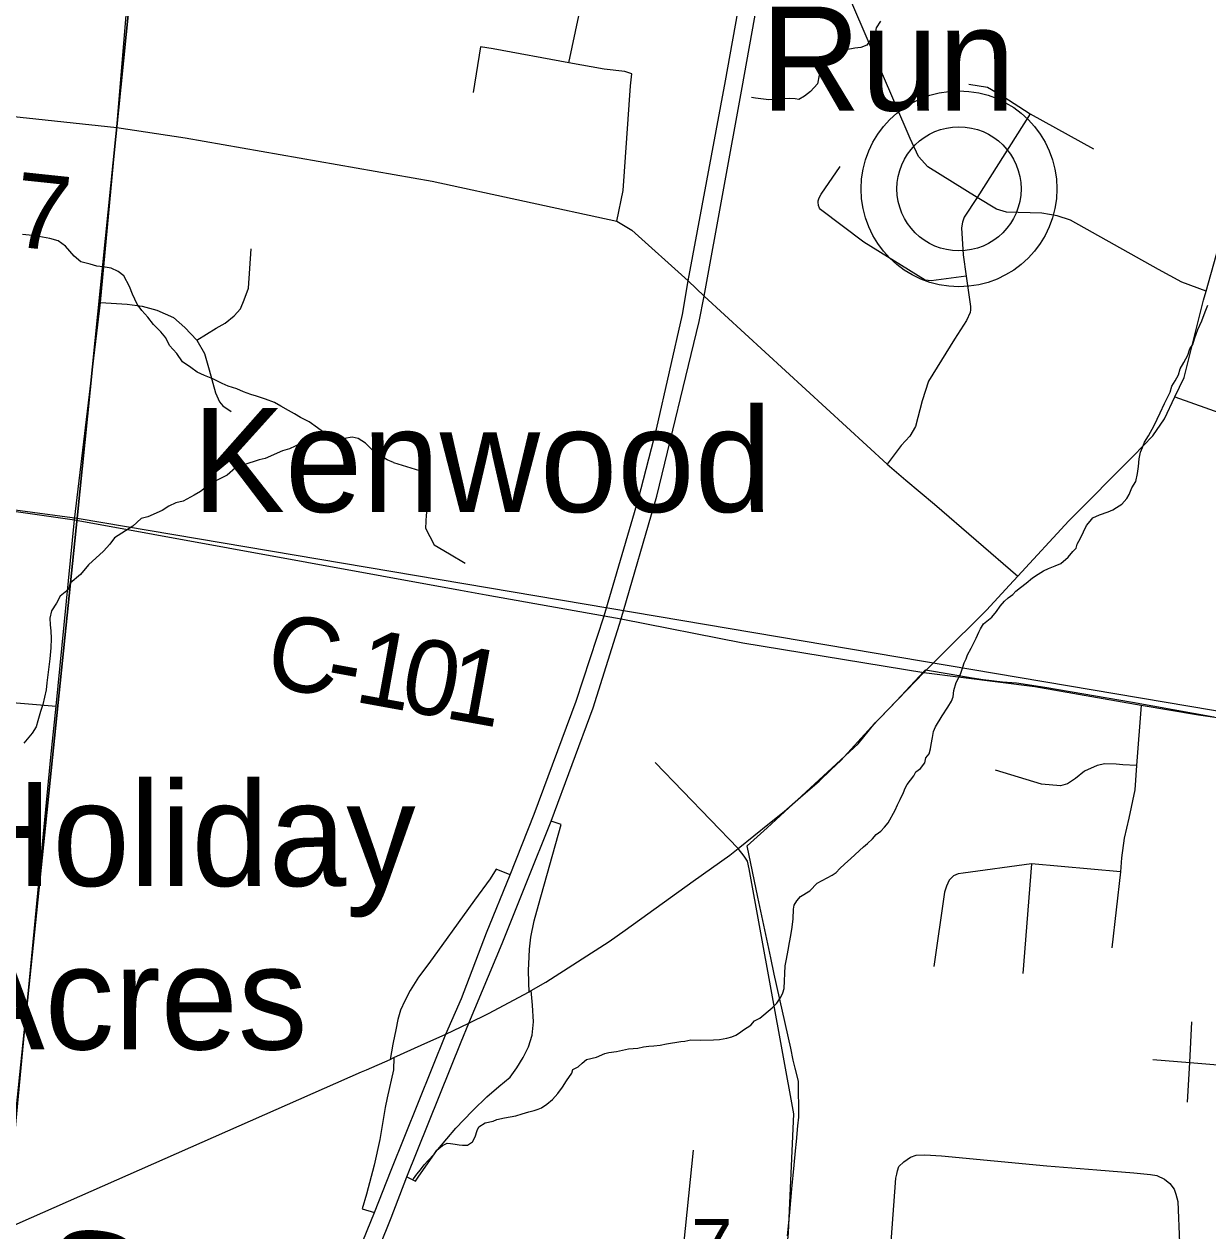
# Model space of a CAD drawing. Extents: x 0 to 34, y 0 to 22.
# Drawn here: x 3.9828 to 4.4325, y 20.1554 to 20.6139 of the extents above; entities that cross this region are included whole.
import ezdxf

# ---------------------------------------------------------------- set-up
doc = ezdxf.new("R2010")
doc.units = 0
for name, color, linetype in [('GM_X_City_Street', 7, 'Continuous'), ('GM_X_Corporation', 7, 'Continuous'), ('GM_X_County_Road', 7, 'Continuous'), ('GM_X_County_Road_Text', 7, 'Continuous'), ('GM_X_Interchange_Ramps', 7, 'Continuous'), ('GM_X_Interstate_Route', 7, 'Continuous'), ('GM_X_Minor_River', 7, 'Continuous'), ('GM_X_Section', 7, 'Continuous'), ('GM_X_Section_Text', 7, 'Continuous'), ('GM_X_State_Route', 7, 'Continuous'), ('GM_X_State_Shield', 7, 'Continuous'), ('GM_X_Township_Road', 7, 'Continuous'), ('GM_X_Unincorporated', 7, 'Continuous'), ('GM_X_Unincorporated_Location', 7, 'Continuous'), ('GM_X_Unincorporated_Text', 7, 'Continuous'), ('GM_X_US_Route', 7, 'Continuous')]:
    doc.layers.add(name, color=color, linetype=linetype)

msp = doc.modelspace()

# ---------------------------------------------------------------- linework, layer by layer
at = {"layer": 'GM_X_City_Street'}
msp.add_line((4.36553, 20.29487), (4.36217, 20.25325), dxfattribs=at)
for points in [[(4.4072, 20.35519), (4.4054, 20.33217), (4.40468, 20.32302), (4.40242, 20.31224), (4.40072, 20.30458), (4.39965, 20.29713), (4.39934, 20.29179), (4.39595, 20.26291)], [(4.4054, 20.33217), (4.40016, 20.33248), (4.39759, 20.33268), (4.39338, 20.33279), (4.3904, 20.33227), (4.38567, 20.33001), (4.38218, 20.32724), (4.3792, 20.32529), (4.37653, 20.32446), (4.36933, 20.32508), (4.35176, 20.33042)], [(4.39934, 20.29179), (4.36553, 20.29487), (4.33948, 20.29127), (4.33769, 20.2911), (4.33583, 20.29035), (4.33425, 20.28865), (4.33314, 20.28644), (4.33247, 20.28404), (4.32833, 20.25583)], [(4.42474, 20.20429), (4.42558, 20.21936), (4.42645, 20.23489)], [(4.41155, 20.22051), (4.42558, 20.21936), (4.46672, 20.21601)], [(4.31219, 20.15133), (4.31396, 20.17542), (4.31437, 20.17694), (4.31463, 20.1783), (4.31511, 20.17986), (4.31704, 20.18163), (4.31947, 20.18343), (4.32164, 20.18422), (4.32493, 20.1843), (4.3313, 20.18393), (4.37129, 20.18015), (4.39028, 20.17867), (4.40442, 20.17743), (4.41071, 20.1769), (4.41309, 20.17641), (4.41605, 20.17505), (4.41803, 20.17341), (4.41963, 20.17127), (4.42037, 20.16938), (4.42103, 20.16662), (4.42168, 20.15084)]]:
    msp.add_lwpolyline(points, dxfattribs=at)
at = {"layer": 'GM_X_Corporation'}
msp.add_lwpolyline([(4.27281, 20.1535), (4.27366, 20.16246), (4.2741, 20.16703), (4.27451, 20.17142), (4.27499, 20.17646), (4.27536, 20.18037), (4.27589, 20.18589), (4.27621, 20.18933), (4.27678, 20.19531), (4.27709, 20.19858), (4.27694, 20.21224), (4.27568, 20.21721), (4.27499, 20.22028), (4.27408, 20.22483), (4.26778, 20.253), (4.26648, 20.25912), (4.26159, 20.28217), (4.25745, 20.30169), (4.26514, 20.30853), (4.29967, 20.3405), (4.30614, 20.34838), (4.3077, 20.35002), (4.31416, 20.35682), (4.32455, 20.36788), (4.32521, 20.36856), (4.33493, 20.36689), (4.34295, 20.36551), (4.34711, 20.3649), (4.35441, 20.36398), (4.35974, 20.36361), (4.37053, 20.36197), (4.40387, 20.35625), (4.43474, 20.35069)], dxfattribs=at)
at = {"layer": 'GM_X_County_Road'}
msp.add_line((4.00194, 20.42555), (4.1486, 20.39881), dxfattribs=at)
for points in [[(4.00194, 20.42555), (4.01183, 20.50815), (4.01801, 20.57463), (4.0243, 20.64932), (4.0275, 20.67758), (4.0382, 20.77323), (4.03907, 20.78354), (4.03949, 20.78854)], [(3.75519, 20.60176), (3.79941, 20.59761), (3.83937, 20.59356), (3.84712, 20.59266), (3.88022, 20.58919), (3.91479, 20.58571), (3.95045, 20.58184), (4.01801, 20.57463)], [(4.01801, 20.57463), (4.04398, 20.57061), (4.13783, 20.55418), (4.20798, 20.53897), (4.21365, 20.53558), (4.23513, 20.51628), (4.24121, 20.51049), (4.31068, 20.44666), (4.31777, 20.44059), (4.32864, 20.43149), (4.36027, 20.4041)], [(4.41995, 20.47233), (4.45594, 20.45945), (4.45995, 20.45805)], [(3.72318, 20.4638), (3.7389, 20.46164), (3.7495, 20.46041), (3.76841, 20.45778), (3.7832, 20.45581), (3.79619, 20.454), (3.82463, 20.4503), (3.8511, 20.44668), (3.86458, 20.44483), (3.92402, 20.43665), (4.00194, 20.42555)], [(3.97584, 20.15616), (3.97938, 20.19313), (3.98298, 20.23082), (3.99299, 20.33535), (3.99504, 20.35476), (4.00194, 20.42555)], [(4.1486, 20.39881), (4.15837, 20.39703), (4.2032, 20.38903), (4.20961, 20.38789), (4.25586, 20.37886), (4.32458, 20.3676)], [(4.32458, 20.3676), (4.36675, 20.36218), (4.4072, 20.35519), (4.4289, 20.35149), (4.44394, 20.34936), (4.44933, 20.34898)], [(4.24779, 19.89317), (4.26262, 20.03839), (4.27109, 20.13267), (4.27314, 20.1547), (4.27515, 20.19987), (4.25821, 20.29293), (4.2576, 20.29591), (4.25636, 20.29774), (4.25412, 20.30065)]]:
    msp.add_lwpolyline(points, dxfattribs=at)
at = {"layer": 'GM_X_Interchange_Ramps'}
msp.add_line((4.15395, 20.281), (4.14542, 20.26928), dxfattribs=at)
for points in [[(4.17462, 20.24623), (4.17449, 20.24972), (4.17449, 20.24993), (4.17445, 20.25432), (4.1747, 20.25954), (4.17482, 20.26242), (4.17535, 20.26702), (4.17663, 20.27323), (4.17818, 20.27915), (4.18678, 20.30985), (4.18299, 20.31109)], [(4.16744, 20.29065), (4.16216, 20.2928), (4.15985, 20.28912), (4.15395, 20.281)], [(4.14542, 20.26928), (4.14378, 20.26702), (4.13653, 20.25701), (4.13261, 20.25177), (4.12942, 20.24673), (4.12747, 20.24276), (4.12579, 20.23926), (4.12484, 20.23576), (4.12402, 20.23184), (4.12305, 20.22701), (4.12291, 20.22634), (4.12181, 20.22052)], [(4.15308, 20.20096), (4.15345, 20.20134), (4.15853, 20.20633), (4.16315, 20.21023), (4.16743, 20.21379), (4.17004, 20.21736), (4.17237, 20.22128), (4.17447, 20.22532), (4.17586, 20.22976), (4.17631, 20.23483), (4.17588, 20.24121), (4.17549, 20.24669)], [(4.12329, 20.22126), (4.12309, 20.21663), (4.12076, 20.206), (4.12002, 20.20228), (4.11797, 20.19018), (4.11575, 20.18037), (4.11289, 20.16942), (4.11127, 20.16375), (4.11588, 20.16239)], [(4.14, 20.18635), (4.14678, 20.19451), (4.15308, 20.20096)], [(4.12821, 20.17596), (4.13151, 20.17427), (4.1327, 20.17615), (4.13964, 20.18592), (4.14, 20.18635)]]:
    msp.add_lwpolyline(points, dxfattribs=at)
at = {"layer": 'GM_X_Interstate_Route'}
for points in [[(4.10569, 20.13725), (4.11588, 20.16239), (4.1222, 20.17847), (4.14304, 20.23011), (4.14895, 20.24368), (4.15849, 20.26868), (4.16744, 20.29065), (4.17662, 20.31368), (4.19256, 20.35667), (4.2032, 20.38903), (4.21618, 20.43357), (4.22309, 20.45994), (4.23291, 20.50351), (4.23513, 20.51628), (4.24925, 20.59234), (4.27239, 20.72152), (4.28895, 20.81079), (4.29422, 20.83832), (4.29772, 20.85553), (4.30167, 20.87122), (4.30474, 20.88372), (4.30862, 20.89772), (4.30932, 20.9)], [(4.14888, 20.22728), (4.1517, 20.23428), (4.16438, 20.26459), (4.17381, 20.28806), (4.18299, 20.31109), (4.19892, 20.35408), (4.20961, 20.38789), (4.22316, 20.43457), (4.23928, 20.50092), (4.24121, 20.51049), (4.25562, 20.58975), (4.27876, 20.71893), (4.29532, 20.8082), (4.30058, 20.83572), (4.30409, 20.85294), (4.30804, 20.86862), (4.31111, 20.88112), (4.31539, 20.89527), (4.31666, 20.9)], [(3.90698, 19.98617), (3.95163, 20.00129), (3.96119, 20.00456), (3.98837, 20.01368), (4.00153, 20.0185), (4.01162, 20.02278), (4.02083, 20.02728), (4.03322, 20.03451), (4.04441, 20.04208), (4.05384, 20.04943), (4.06404, 20.05875), (4.0738, 20.06895), (4.08016, 20.07674), (4.08805, 20.08715), (4.0943, 20.09735), (4.10165, 20.11051), (4.10922, 20.12795), (4.12227, 20.16041), (4.12821, 20.17596), (4.14888, 20.22728)]]:
    msp.add_lwpolyline(points, dxfattribs=at)
at = {"layer": 'GM_X_Minor_River'}
for points in [[(4.30811, 20.61499), (4.30647, 20.6124), (4.30622, 20.61108), (4.30579, 20.60976), (4.30397, 20.60736), (4.30295, 20.60588), (4.30062, 20.60502), (4.29832, 20.60474), (4.29504, 20.6041), (4.29214, 20.60327), (4.29018, 20.60221), (4.28773, 20.59831), (4.28489, 20.59443), (4.28419, 20.59122), (4.28158, 20.58829), (4.27921, 20.58648), (4.27706, 20.58523), (4.27573, 20.58548), (4.27363, 20.58556), (4.27133, 20.58546), (4.26902, 20.58517), (4.2675, 20.58523), (4.26577, 20.58511), (4.26064, 20.5857), (4.25912, 20.58595)], [(4.12318, 20.44732), (4.12075, 20.44837), (4.11816, 20.45), (4.11593, 20.45123), (4.11245, 20.45461), (4.10967, 20.45643), (4.10741, 20.45691), (4.10454, 20.45646), (4.10226, 20.45655), (4.10001, 20.45721), (4.09757, 20.45808), (4.09425, 20.46049), (4.09111, 20.46272), (4.08775, 20.46438), (4.08553, 20.4658), (4.0833, 20.46703), (4.08032, 20.46868), (4.07791, 20.47011), (4.07454, 20.47139), (4.07116, 20.47248), (4.06891, 20.47314), (4.0661, 20.47421), (4.06367, 20.47526), (4.06029, 20.47635), (4.05805, 20.47739), (4.05451, 20.47906), (4.05133, 20.48033), (4.04853, 20.48159), (4.04613, 20.4834), (4.04299, 20.48562), (4.04083, 20.48875), (4.0381, 20.49172), (4.03669, 20.49463), (4.0347, 20.49699), (4.03195, 20.49976), (4.02978, 20.50252), (4.0276, 20.50508), (4.0258, 20.50743), (4.02405, 20.51131), (4.02283, 20.51421), (4.02071, 20.51829), (4.0185, 20.5199), (4.01589, 20.52115), (4.01287, 20.52165), (4.01041, 20.52195), (4.00796, 20.52262), (4.00439, 20.52353), (4.00182, 20.52573), (3.99854, 20.52947), (3.99577, 20.53149), (3.99258, 20.53238), (3.98843, 20.53312), (3.98598, 20.53361), (3.98219, 20.53395)], [(4.38242, 20.41482), (4.38286, 20.41632), (4.3841, 20.41856), (4.38641, 20.42341), (4.38781, 20.42507), (4.38882, 20.42636), (4.39135, 20.4274), (4.39465, 20.4286), (4.3964, 20.42929), (4.39777, 20.43018), (4.39974, 20.43144), (4.40174, 20.43364), (4.40257, 20.43513), (4.40363, 20.43775), (4.40507, 20.44016), (4.40577, 20.44318), (4.40607, 20.44583), (4.40638, 20.44867), (4.40687, 20.45131), (4.4077, 20.45299), (4.40836, 20.45506), (4.40999, 20.45746), (4.41206, 20.46137), (4.41437, 20.46623), (4.41604, 20.46977), (4.41709, 20.47201), (4.41813, 20.47406), (4.4188, 20.47632), (4.42003, 20.47836), (4.42127, 20.4806), (4.42193, 20.48285), (4.42337, 20.48527), (4.42483, 20.48806), (4.42569, 20.4905), (4.42672, 20.49217), (4.42738, 20.49424), (4.42867, 20.4978), (4.43015, 20.50116), (4.43143, 20.50453), (4.4325, 20.50715)], [(4.09706, 20.45845), (4.09142, 20.45624), (4.08793, 20.45449), (4.08368, 20.45257), (4.08098, 20.45173), (4.07441, 20.44878), (4.07211, 20.4483), (4.06634, 20.44645), (4.06306, 20.44526), (4.05991, 20.44254), (4.05584, 20.44043), (4.05292, 20.43865), (4.04979, 20.43631), (4.04745, 20.43488), (4.04318, 20.43259), (4.04049, 20.43194), (4.03778, 20.43072), (4.03525, 20.42912), (4.02984, 20.42668), (4.02734, 20.42603), (4.02418, 20.42312), (4.0199, 20.42044), (4.01717, 20.41866), (4.01536, 20.41626), (4.01298, 20.4137), (4.00727, 20.40843), (4.00427, 20.40475), (4.00034, 20.40149), (3.99968, 20.39905), (3.99654, 20.39652), (3.9951, 20.39392), (3.99328, 20.39095), (3.99259, 20.38813), (3.99269, 20.38566), (3.99298, 20.38336), (3.99306, 20.38051), (3.99291, 20.3769), (3.99256, 20.37274), (3.99144, 20.36366), (3.99115, 20.36101), (3.98998, 20.35536), (3.98911, 20.35274), (3.98802, 20.34917), (3.98736, 20.34692), (3.98594, 20.34451), (3.98275, 20.34065)], [(4.12318, 20.44732), (4.13307, 20.44427), (4.13638, 20.43869), (4.13643, 20.43222), (4.13557, 20.42748), (4.13528, 20.42235), (4.13857, 20.416), (4.14439, 20.41266), (4.1504, 20.40912)], [(4.21591, 20.22483), (4.21804, 20.22531), (4.22015, 20.22561), (4.22207, 20.22572), (4.22438, 20.22601), (4.22688, 20.22648), (4.23227, 20.22741), (4.23381, 20.22754), (4.23612, 20.22802), (4.23974, 20.22787), (4.24472, 20.22805), (4.24702, 20.22815), (4.24972, 20.22862), (4.25165, 20.22911), (4.25321, 20.22981), (4.25458, 20.2307), (4.25615, 20.23178), (4.2589, 20.23357), (4.26031, 20.23523), (4.26227, 20.23629), (4.26701, 20.2401), (4.26881, 20.24193), (4.27024, 20.24415), (4.27107, 20.24583), (4.27152, 20.24752), (4.27188, 20.25607), (4.27237, 20.25871), (4.27308, 20.2621), (4.27358, 20.26493), (4.27407, 20.26758), (4.27459, 20.27079), (4.27491, 20.27401), (4.27506, 20.27762), (4.27531, 20.27913), (4.27634, 20.2808), (4.27774, 20.28245), (4.28127, 20.28459), (4.28407, 20.28753), (4.28974, 20.29053), (4.29131, 20.29161), (4.29271, 20.29308), (4.2945, 20.29472), (4.29688, 20.2969), (4.30165, 20.30128), (4.30323, 20.30255), (4.30503, 20.30438), (4.30643, 20.30603), (4.30821, 20.30729), (4.30961, 20.30876), (4.31101, 20.31041), (4.3137, 20.31525), (4.31455, 20.31731), (4.31559, 20.31936), (4.31684, 20.32197), (4.31748, 20.32366), (4.3183, 20.32495), (4.32073, 20.32828), (4.32156, 20.32977), (4.32333, 20.33103), (4.32495, 20.33325), (4.32541, 20.33513), (4.32662, 20.3366), (4.32708, 20.33849), (4.32734, 20.34019), (4.32783, 20.34283), (4.32831, 20.34509), (4.32896, 20.34697), (4.33161, 20.35105), (4.33366, 20.35439), (4.33509, 20.35661), (4.33574, 20.3583), (4.33603, 20.36076), (4.33692, 20.36377), (4.33858, 20.36693), (4.33945, 20.36956), (4.3399, 20.37125), (4.34073, 20.37274), (4.34118, 20.37425), (4.34262, 20.37685), (4.3445, 20.38058), (4.34554, 20.38282), (4.34617, 20.38413), (4.3472, 20.38599), (4.35037, 20.38852), (4.35218, 20.39073), (4.3536, 20.39277), (4.35521, 20.39461), (4.3566, 20.39588), (4.35837, 20.39714), (4.35957, 20.39843), (4.36135, 20.39988), (4.36352, 20.4015), (4.3659, 20.4035), (4.36806, 20.40493), (4.37002, 20.40619), (4.37197, 20.40706), (4.3745, 20.4081), (4.37664, 20.40897), (4.37941, 20.41133), (4.38122, 20.41354), (4.38242, 20.41482)], [(4.13069, 20.17512), (4.13071, 20.17517), (4.13194, 20.17702), (4.13334, 20.17868), (4.13476, 20.18052), (4.13615, 20.18199), (4.13855, 20.18456), (4.13957, 20.18604), (4.14175, 20.18785), (4.1435, 20.18873), (4.14484, 20.18868), (4.14655, 20.18842), (4.14807, 20.18817), (4.1494, 20.18793), (4.15131, 20.18804), (4.15309, 20.1893), (4.15412, 20.19116), (4.15498, 20.1936), (4.15561, 20.19491), (4.15797, 20.19652), (4.16106, 20.19716), (4.16242, 20.19768), (4.16531, 20.19832), (4.16743, 20.19881), (4.16955, 20.1991), (4.17207, 20.19995), (4.17458, 20.20061), (4.17651, 20.20111), (4.17806, 20.20162), (4.17942, 20.20213), (4.18139, 20.20358), (4.18357, 20.20539), (4.18557, 20.20759), (4.18739, 20.20999), (4.18883, 20.21241), (4.19087, 20.21537), (4.1913, 20.21668), (4.19326, 20.21774), (4.19485, 20.2192), (4.19643, 20.22047), (4.20029, 20.22146), (4.20341, 20.22285), (4.20495, 20.22317), (4.20784, 20.22363), (4.21246, 20.22459), (4.21591, 20.22483)]]:
    msp.add_lwpolyline(points, dxfattribs=at)
at = {"layer": 'GM_X_Section'}
for points in [[(3.4808, 20.49635), (4.00293, 20.42622), (3.95103, 19.92358), (3.43084, 19.98722)], [(4.00293, 20.42622), (4.48038, 20.34556), (4.43689, 19.87849), (3.95103, 19.92358)]]:
    msp.add_lwpolyline(points, close=True, dxfattribs=at)
at = {"layer": 'GM_X_State_Route'}
for p, q in [((4.35713, 20.40071), (4.36027, 20.4041)), ((4.32458, 20.3676), (4.33119, 20.37416)), ((4.25412, 20.30065), (4.26596, 20.31027)), ((4.21115, 20.26965), (4.23703, 20.28826)), ((4.17462, 20.24623), (4.17549, 20.24669)), ((4.12329, 20.22126), (4.13369, 20.22592)), ((4.12181, 20.22052), (4.12329, 20.22126)), ((4.11282, 20.21658), (4.12181, 20.22052))]:
    msp.add_line(p, q, dxfattribs=at)
for points in [[(4.43185, 20.51237), (4.43861, 20.53634), (4.44538, 20.55523), (4.45443, 20.57041), (4.46539, 20.58169), (4.48345, 20.59455), (4.49521, 20.60256), (4.50515, 20.60819)], [(4.41995, 20.47233), (4.42344, 20.4796), (4.43088, 20.50893), (4.43185, 20.51237)], [(4.36027, 20.4041), (4.37973, 20.42514), (4.40422, 20.44987), (4.4116, 20.45751), (4.41607, 20.46396), (4.41995, 20.47233)], [(4.33119, 20.37416), (4.34836, 20.39122), (4.35713, 20.40071)], [(4.2893, 20.33053), (4.29306, 20.33411), (4.30465, 20.34694), (4.32458, 20.3676)], [(4.27775, 20.32015), (4.2848, 20.32622), (4.2893, 20.33053)], [(4.26596, 20.31027), (4.27148, 20.31475), (4.27775, 20.32015)], [(4.23703, 20.28826), (4.25084, 20.29818), (4.25412, 20.30065)], [(4.17549, 20.24669), (4.18097, 20.24992), (4.20511, 20.26531), (4.21115, 20.26965)], [(4.13369, 20.22592), (4.14304, 20.23011), (4.1517, 20.23428), (4.15918, 20.23798), (4.17462, 20.24623)], [(3.97584, 20.15616), (4.11103, 20.21579), (4.11282, 20.21658)]]:
    msp.add_lwpolyline(points, dxfattribs=at)
at = {"layer": 'GM_X_State_Shield'}
for points in [[(4.05097, 20.9), (3.52038, 20.9), (3.4808, 20.49635), (4.00293, 20.42622)], [(4.22367, 20.9), (4.05097, 20.9), (4.00293, 20.42622), (4.48038, 20.34556), (4.52837, 20.84401)]]:
    msp.add_lwpolyline(points, close=True, dxfattribs=at)
at = {"layer": 'GM_X_Township_Road'}
for p, q in [((4.25412, 20.30065), (4.22253, 20.33337)), ((4.23698, 20.1861), (4.23204, 20.13828))]:
    msp.add_line(p, q, dxfattribs=at)
for points in [[(4.43185, 20.51237), (4.42256, 20.51581), (4.41371, 20.52061), (4.38034, 20.53932), (4.37528, 20.54109), (4.36947, 20.5421), (4.35594, 20.54248), (4.35215, 20.54362), (4.34485, 20.54805), (4.32611, 20.55967), (4.32257, 20.56359), (4.31941, 20.57042), (4.29726, 20.62198), (4.29658, 20.62486), (4.29764, 20.62939), (4.30447, 20.66669), (4.3108, 20.70133), (4.3153, 20.72589), (4.31579, 20.72733), (4.31662, 20.7285), (4.31766, 20.72926), (4.33547, 20.73547)], [(4.1897, 20.59916), (4.19648, 20.63084), (4.20003, 20.65162), (4.20011, 20.65286), (4.19996, 20.65403), (4.20003, 20.6591), (4.19602, 20.66903), (4.19, 20.68097)], [(4.20798, 20.53897), (4.21036, 20.5507), (4.21317, 20.59042), (4.21367, 20.59503), (4.21106, 20.59583), (4.20315, 20.59671), (4.1897, 20.59916), (4.16102, 20.60446), (4.15613, 20.60519), (4.15343, 20.58783)], [(4.34166, 20.59102), (4.34873, 20.58988), (4.35455, 20.58647), (4.36492, 20.57977), (4.38906, 20.5665)], [(4.36492, 20.57977), (4.34485, 20.54805), (4.33997, 20.54047), (4.33923, 20.53864), (4.33894, 20.5365), (4.33952, 20.52623), (4.34067, 20.51806), (4.34229, 20.50656), (4.34237, 20.50527), (4.34223, 20.50427), (4.34078, 20.5013), (4.33628, 20.49416), (4.32631, 20.47818), (4.3239, 20.47081), (4.32144, 20.46097), (4.31928, 20.45739), (4.31599, 20.45384), (4.31068, 20.44666)], [(4.34067, 20.51806), (4.32738, 20.51637), (4.3251, 20.5166), (4.30182, 20.53107), (4.28539, 20.54346), (4.28496, 20.54392), (4.28457, 20.545), (4.28443, 20.54621), (4.28448, 20.54668), (4.28481, 20.54783), (4.28562, 20.54923), (4.29284, 20.55975)], [(4.04842, 20.49382), (4.05579, 20.49832), (4.05915, 20.50027), (4.06263, 20.50303), (4.065, 20.50573), (4.06642, 20.50909), (4.068, 20.51353), (4.06905, 20.52845)], [(4.01183, 20.50815), (4.02192, 20.50743), (4.02766, 20.50672), (4.03326, 20.50523), (4.03956, 20.5024), (4.04388, 20.49857), (4.04842, 20.49382), (4.0514, 20.48875), (4.05313, 20.48248), (4.05548, 20.47383), (4.05703, 20.47037), (4.05831, 20.46884), (4.06146, 20.46672)], [(3.87708, 20.36687), (3.91457, 20.36246), (3.95292, 20.35854), (3.97397, 20.35654), (3.99504, 20.35476)]]:
    msp.add_lwpolyline(points, dxfattribs=at)
at = {"layer": 'GM_X_Unincorporated'}
for radius in [0.0372, 0.02358]:
    msp.add_circle((4.33794, 20.55128), radius, dxfattribs=at)
at = {"layer": 'GM_X_Unincorporated_Location'}
msp.add_line((4.33794, 20.55128), (4.33794, 20.55128), dxfattribs=at)
at = {"layer": 'GM_X_US_Route'}
for p, q in [((4.35713, 20.40071), (4.36027, 20.4041)), ((4.32458, 20.3676), (4.33119, 20.37416)), ((4.25412, 20.30065), (4.26596, 20.31027)), ((4.21115, 20.26965), (4.23703, 20.28826)), ((4.17462, 20.24623), (4.17549, 20.24669)), ((4.12329, 20.22126), (4.13369, 20.22592)), ((4.12181, 20.22052), (4.12329, 20.22126)), ((4.11282, 20.21658), (4.12181, 20.22052))]:
    msp.add_line(p, q, dxfattribs=at)
for points in [[(4.43185, 20.51237), (4.43861, 20.53634), (4.44538, 20.55523), (4.45443, 20.57041), (4.46539, 20.58169), (4.48345, 20.59455), (4.49521, 20.60256), (4.50515, 20.60819)], [(4.41995, 20.47233), (4.42344, 20.4796), (4.43088, 20.50893), (4.43185, 20.51237)], [(4.36027, 20.4041), (4.37973, 20.42514), (4.40422, 20.44987), (4.4116, 20.45751), (4.41607, 20.46396), (4.41995, 20.47233)], [(4.33119, 20.37416), (4.34836, 20.39122), (4.35713, 20.40071)], [(4.2893, 20.33053), (4.29306, 20.33411), (4.30465, 20.34694), (4.32458, 20.3676)], [(4.27775, 20.32015), (4.2848, 20.32622), (4.2893, 20.33053)], [(4.26596, 20.31027), (4.27148, 20.31475), (4.27775, 20.32015)], [(4.23703, 20.28826), (4.25084, 20.29818), (4.25412, 20.30065)], [(4.17549, 20.24669), (4.18097, 20.24992), (4.20511, 20.26531), (4.21115, 20.26965)], [(4.13369, 20.22592), (4.14304, 20.23011), (4.1517, 20.23428), (4.15918, 20.23798), (4.17462, 20.24623)], [(3.97584, 20.15616), (4.11103, 20.21579), (4.11282, 20.21658)]]:
    msp.add_lwpolyline(points, dxfattribs=at)

# ---------------------------------------------------------------- texts
at = {"layer": 'GM_X_County_Road_Text'}
for s, height, rotation, p in [('C-267', 0.028409, 353.9635, (3.89592, 20.53821)), ('C', 0.02841, 349.732, (4.0735, 20.36277)), ('1', 0.02841, 349.7319, (4.10767, 20.35658)), ('0', 0.02841, 349.7293, (4.12475, 20.35348)), ('1', 0.02841, 349.7114, (4.14183, 20.35039)), ('-', 0.02841, 349.732, (4.09629, 20.35864)), ('C-269', 0.028409, 84.4812, (4.01584, 20.05295))]:
    msp.add_text(s, height=height, rotation=rotation, dxfattribs=at).set_placement(p)
at = {"layer": 'GM_X_Section_Text'}
msp.add_text('7', height=0.02093, rotation=0, dxfattribs=at).set_placement((4.23629, 20.13903))
at = {"layer": 'GM_X_Unincorporated_Text'}
for s, p in [('Run', (4.26254, 20.58101)), ('Kenwood', (4.04671, 20.42851)), ('Holiday', (3.95546, 20.28643)), ('Acres', (3.95546, 20.22434))]:
    msp.add_text(s, height=0.039489, rotation=0, dxfattribs=at).set_placement(p)

doc.saveas('drawing.dxf')
